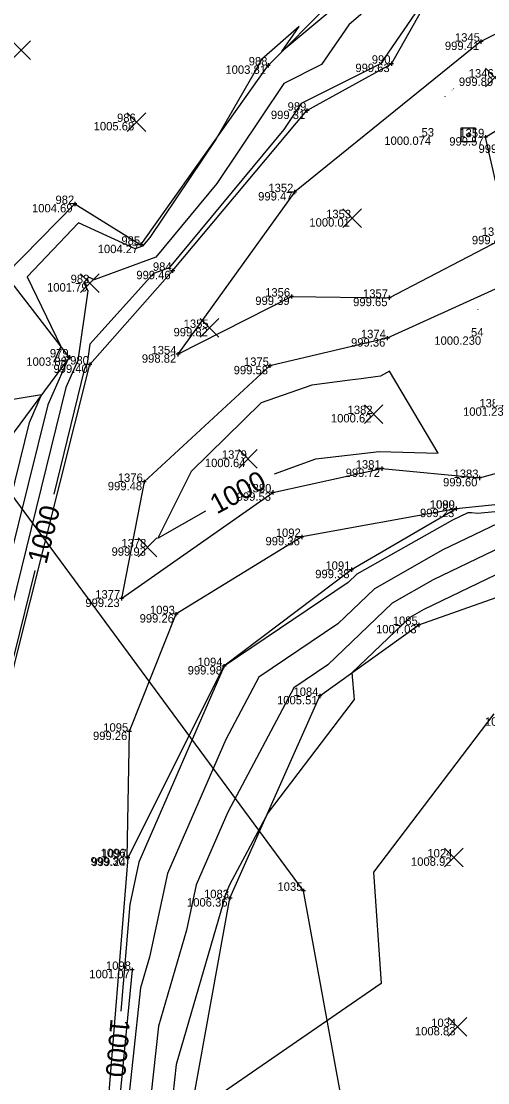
# Model space of a CAD drawing. Extents: x 2354693 to 2355622, y 637071 to 710080.
# Drawn here: x 2355257.5 to 2355324.2, y 709182.9 to 709334.6 of the extents above; entities that cross this region are included whole.
import ezdxf

# ---------------------------------------------------------------- set-up
doc = ezdxf.new("R2010")
doc.units = 0
for name, color, linetype in [('BR_P_Sub_Hidden', 7, 'Continuous'), ('BR_X_SV_Pier_Text', 7, 'Continuous'), ('DT_X_Contour_Major', 7, 'Continuous'), ('DT_X_Contour_Minor', 7, 'Continuous'), ('DT_X_Spot_Elev', 7, 'Continuous'), ('HY_X_Water_Edge', 7, 'Continuous'), ('SV_X_Break_Lines', 7, 'Continuous'), ('SV_X_Control_Cells_Found', 7, 'Continuous'), ('SV_X_Random_Point', 7, 'Continuous'), ('SV_X_Shot_Marker', 7, 'Continuous'), ('SV_X_Text_Elevation', 7, 'Continuous'), ('SV_X_Text_Name', 7, 'Continuous'), ('SV_X_Toe_of_Slope', 7, 'Continuous'), ('SV_X_Top_of_Bank', 7, 'Continuous'), ('VG_X_Tree_Line_Rt', 7, 'Continuous')]:
    doc.layers.add(name, color=color, linetype=linetype)

msp = doc.modelspace()

# ---------------------------------------------------------------- linework, layer by layer
at = {"layer": 'BR_P_Sub_Hidden'}
for points in [[(2355308.85, 709283.88), (2355308.16, 709283.78), (2355306.08, 709283.5), (2355304.5, 709283.29), (2355299.03, 709282.56), (2355291.81, 709280.05), (2355281.77, 709270.26), (2355277.03, 709260.71), (2355283.87, 709264.65)], [(2355293.71, 709269.93), (2355299.64, 709272.06), (2355308.68, 709273.09), (2355317.11, 709272.88), (2355310.14, 709284.57), (2355308.85, 709283.88)]]:
    msp.add_lwpolyline(points, dxfattribs=at)
at = {"layer": 'DT_X_Contour_Major'}
for points in [[(2355321.43, 709340.39), (2355320.59, 709340.2), (2355320.5, 709340.02), (2355317.25, 709340.56), (2355317.25, 709340.56), (2355317.21, 709340.59), (2355317.1, 709340.49), (2355308.88, 709328.46), (2355297.5, 709322.78), (2355295.04, 709319.11), (2355278.63, 709299.33), (2355276.4, 709298.5), (2355267.3, 709288.45), (2355266.91, 709285.66), (2355266.51, 709284.78), (2355262.13, 709266.99)], [(2355321.43, 709340.39), (2355320.59, 709340.2), (2355320.5, 709340.02), (2355317.25, 709340.56), (2355317.25, 709340.56), (2355317.21, 709340.59), (2355317.1, 709340.49), (2355308.88, 709328.46), (2355297.5, 709322.78), (2355295.04, 709319.11), (2355278.63, 709299.33), (2355276.4, 709298.5), (2355267.3, 709288.45), (2355266.91, 709285.66), (2355266.51, 709284.78), (2355262.13, 709266.99)], [(2355308.85, 709283.88), (2355308.16, 709283.78), (2355306.08, 709283.5), (2355304.5, 709283.29), (2355299.03, 709282.56), (2355291.81, 709280.05), (2355281.77, 709270.26), (2355277.03, 709260.71), (2355283.87, 709264.65)], [(2355293.71, 709269.93), (2355299.64, 709272.06), (2355308.68, 709273.09), (2355317.11, 709272.88), (2355310.14, 709284.57), (2355308.85, 709283.88)], [(2355328.11, 709264.75), (2355322.77, 709264.26), (2355321.89, 709264.33), (2355321.33, 709264.35), (2355319.14, 709263.3), (2355305.5, 709255.57), (2355304.26, 709254.39), (2355286.53, 709242.43), (2355286.48, 709242.36), (2355274.31, 709214.47), (2355273, 709208.41), (2355271.74, 709193.19)], [(2355328.11, 709264.75), (2355322.77, 709264.26), (2355321.89, 709264.33), (2355321.33, 709264.35), (2355319.14, 709263.3), (2355305.5, 709255.57), (2355304.26, 709254.39), (2355286.53, 709242.43), (2355286.48, 709242.36), (2355274.31, 709214.47), (2355273, 709208.41), (2355271.74, 709193.19)], [(2355259.45, 709256.12), (2355256.53, 709244.3), (2355256.24, 709243.32), (2355255.21, 709238.35), (2355247.24, 709204.27), (2355240.26, 709205.95), (2355238.9, 709200.49), (2355236.53, 709200.69), (2355234.37, 709199.64), (2355221.59, 709197.85), (2355209.81, 709203.68)], [(2355259.45, 709256.12), (2355256.53, 709244.3), (2355256.24, 709243.32), (2355255.21, 709238.35), (2355247.24, 709204.27), (2355240.26, 709205.95), (2355238.9, 709200.49), (2355236.53, 709200.69), (2355234.37, 709199.64), (2355221.59, 709197.85), (2355209.81, 709203.68)]]:
    msp.add_lwpolyline(points, dxfattribs=at)
at = {"layer": 'DT_X_Contour_Minor'}
for points in [[(2355326.53, 709342.57), (2355320.94, 709341.33), (2355320.35, 709340.1), (2355318.58, 709340.39), (2355318.48, 709340.45), (2355314.55, 709342.82), (2355314.31, 709342.97), (2355312.91, 709343.83), (2355311.95, 709344.59), (2355294.76, 709330.21), (2355297.24, 709333.79), (2355291.85, 709329.11), (2355290.92, 709327.42), (2355285.35, 709317.76), (2355275.87, 709303.68), (2355274.83, 709302.42), (2355273.77, 709302.03), (2355265.66, 709305.78), (2355258.36, 709298.04), (2355263.17, 709288.1), (2355262.13, 709285.92), (2355264.15, 709286.24), (2355261.28, 709279.75), (2355255.69, 709257.09)], [(2355326.53, 709342.57), (2355320.94, 709341.33), (2355320.35, 709340.1), (2355318.58, 709340.39), (2355318.48, 709340.45), (2355314.55, 709342.82), (2355314.31, 709342.97), (2355312.91, 709343.83), (2355311.95, 709344.59), (2355294.76, 709330.21), (2355297.24, 709333.79), (2355291.85, 709329.11), (2355290.92, 709327.42), (2355285.35, 709317.76), (2355275.87, 709303.68), (2355274.83, 709302.42), (2355273.77, 709302.03), (2355265.66, 709305.78), (2355258.36, 709298.04), (2355263.17, 709288.1), (2355262.13, 709285.92), (2355264.15, 709286.24), (2355261.28, 709279.75), (2355255.69, 709257.09)], [(2355323.98, 709341.48), (2355320.76, 709340.76), (2355320.42, 709340.06), (2355317.91, 709340.48), (2355317.86, 709340.51), (2355314.31, 709342.64), (2355304.35, 709334.06), (2355300.45, 709328.35), (2355295.04, 709325.64), (2355285.45, 709311.4), (2355276.73, 709300.87), (2355267.93, 709297.62), (2355267.15, 709297.98), (2355266.44, 709297.23), (2355267.01, 709296.07), (2355265.6, 709286.11), (2355263.89, 709282.26), (2355256.11, 709250.69)], [(2355323.98, 709341.48), (2355320.76, 709340.76), (2355320.42, 709340.06), (2355317.91, 709340.48), (2355317.86, 709340.51), (2355314.31, 709342.64), (2355304.35, 709334.06), (2355300.45, 709328.35), (2355295.04, 709325.64), (2355285.45, 709311.4), (2355276.73, 709300.87), (2355267.93, 709297.62), (2355267.15, 709297.98), (2355266.44, 709297.23), (2355267.01, 709296.07), (2355265.6, 709286.11), (2355263.89, 709282.26), (2355256.11, 709250.69)], [(2355258.66, 709277.24), (2355260.4, 709281.18), (2355246.4, 709278.91), (2355245.09, 709279.12), (2355242.59, 709271.24), (2355232.14, 709270.2), (2355237.45, 709251.15), (2355244.48, 709247.85), (2355245.62, 709241.89), (2355244.67, 709227.63), (2355248.78, 709240.19), (2355250.1, 709246.57), (2355255.27, 709263.49), (2355258.66, 709277.24)], [(2355258.66, 709277.24), (2355260.4, 709281.18), (2355246.4, 709278.91), (2355245.09, 709279.12), (2355242.59, 709271.24), (2355232.14, 709270.2), (2355237.45, 709251.15), (2355244.48, 709247.85), (2355245.62, 709241.89), (2355244.67, 709227.63), (2355248.78, 709240.19), (2355250.1, 709246.57), (2355255.27, 709263.49), (2355258.66, 709277.24)], [(2355325.65, 709262.82), (2355317.77, 709259.04), (2355308.02, 709253.51), (2355302.78, 709248.51), (2355291.49, 709240.89), (2355286.75, 709231.97), (2355278.41, 709212.85), (2355275.83, 709200.88), (2355274.55, 709196.51), (2355272.35, 709176.11)], [(2355325.65, 709262.82), (2355317.77, 709259.04), (2355308.02, 709253.51), (2355302.78, 709248.51), (2355291.49, 709240.89), (2355286.75, 709231.97), (2355278.41, 709212.85), (2355275.83, 709200.88), (2355274.55, 709196.51), (2355272.35, 709176.11)], [(2355329.97, 709261.3), (2355316.41, 709254.78), (2355310.53, 709251.45), (2355301.31, 709242.63), (2355296.45, 709239.35), (2355287.02, 709221.58), (2355282.5, 709211.23), (2355281.11, 709204.74), (2355277.11, 709191.02), (2355275.65, 709177.54)], [(2355329.97, 709261.3), (2355316.41, 709254.78), (2355310.53, 709251.45), (2355301.31, 709242.63), (2355296.45, 709239.35), (2355287.02, 709221.58), (2355282.5, 709211.23), (2355281.11, 709204.74), (2355277.11, 709191.02), (2355275.65, 709177.54)], [(2355334.29, 709259.77), (2355315.04, 709250.52), (2355313.05, 709249.39), (2355304.76, 709241.47), (2355305.1, 709237.69), (2355302.95, 709234.87), (2355292.79, 709221.56), (2355287.29, 709211.19), (2355286.6, 709209.61), (2355286.39, 709208.61), (2355279.66, 709185.54), (2355278.95, 709178.98)], [(2355334.29, 709259.77), (2355315.04, 709250.52), (2355313.05, 709249.39), (2355304.76, 709241.47), (2355305.1, 709237.69), (2355302.95, 709234.87), (2355292.79, 709221.56), (2355287.29, 709211.19), (2355286.6, 709209.61), (2355286.39, 709208.61), (2355279.66, 709185.54), (2355278.95, 709178.98)], [(2355325.08, 709235.63), (2355314.19, 709221.34), (2355307.85, 709213.04), (2355308.94, 709197.1), (2355286.27, 709181.51)], [(2355325.08, 709235.63), (2355314.19, 709221.34), (2355307.85, 709213.04), (2355308.94, 709197.1), (2355286.27, 709181.51)]]:
    msp.add_lwpolyline(points, dxfattribs=at)
at = {"layer": 'HY_X_Water_Edge'}
for points in [[(2355099.14, 709490.23), (2355112.83, 709450.59), (2355116.9, 709430.14), (2355110.74, 709408.55), (2355107.27, 709364.38), (2355126.09, 709328.02), (2355146.4, 709319.01), (2355178.16, 709243.86), (2355207.27, 709238.41), (2355228.23, 709233.04), (2355237.12, 709206.89), (2355247.9, 709203.67), (2355256.61, 709243.12), (2355267.3, 709285.53), (2355279.14, 709298.91), (2355298.35, 709321.78), (2355310.42, 709328.49), (2355317.24, 709340.56)], [(2355359.12, 709336.96), (2355357.91, 709341.69), (2355351.85, 709345.87), (2355323.23, 709331.64), (2355296.55, 709310.15), (2355279.9, 709286.98), (2355296.13, 709295.23), (2355310.1, 709295.06), (2355327.1, 709303.9), (2355323.88, 709317.99), (2355329.6, 709321.57), (2355359.12, 709336.96)], [(2355338.24, 709293.81), (2355335.55, 709300.96), (2355309.84, 709289.28), (2355293.06, 709285.33), (2355275.06, 709268.76), (2355271.82, 709252.1), (2355293.45, 709267.26), (2355309.04, 709270.66), (2355323.01, 709269.32), (2355355.38, 709278.14), (2355366.3, 709291.81), (2355368.89, 709301.06)], [(2355342.79, 709267.27), (2355319.66, 709264.93)], [(2355319.66, 709264.93), (2355297.62, 709260.9), (2355279.61, 709249.87), (2355272.94, 709233.09), (2355272.6, 709215.17)], [(2355272.75, 709215.1), (2355272.74, 709215.09), (2355269.55, 709175.73), (2355269.77, 709147.81), (2355269.19, 709105.65), (2355274.67, 709084.44), (2355274.45, 709045.7), (2355249.64, 708995.53), (2355233.3, 708975.07), (2355214.48, 708950.61), (2355202.85, 708934.67), (2355185.21, 708913.18), (2355155.78, 708878.52), (2355144.35, 708868.9), (2355107.99, 708834.31)]]:
    msp.add_lwpolyline(points, dxfattribs=at)
at = {"layer": 'SV_X_Break_Lines'}
msp.add_lwpolyline([(2355288.47, 709157.1), (2355279.67, 709145.96), (2355282.08, 709180.34), (2355287.34, 709209.31), (2355300.19, 709238.19), (2355314.34, 709248.33), (2355340.5, 709257.58), (2355343.4, 709262.66)], dxfattribs=at)
at = {"layer": 'SV_X_Control_Cells_Found'}
msp.add_lwpolyline([(2355320.41, 709319.32), (2355322.39, 709319.32), (2355322.39, 709317.34), (2355320.41, 709317.34), (2355320.41, 709319.32)], dxfattribs=at)
msp.add_circle((2355321.4, 709318.33), 0.2, dxfattribs=at)
at = {"layer": 'SV_X_Random_Point'}
for p, q in [((2355256.17, 709329.09), (2355258.84, 709331.76)), ((2355256.17, 709331.76), (2355258.84, 709329.09)), ((2355323.9, 709325.17), (2355326.57, 709327.84)), ((2355323.9, 709327.84), (2355326.57, 709325.17)), ((2355272.66, 709318.82), (2355275.33, 709321.49)), ((2355272.66, 709321.49), (2355275.33, 709318.82)), ((2355303.48, 709305.09), (2355306.14, 709307.76)), ((2355303.48, 709307.76), (2355306.14, 709305.09)), ((2355265.97, 709295.81), (2355268.64, 709298.48)), ((2355265.97, 709298.48), (2355268.64, 709295.81)), ((2355283.1, 709289.41), (2355285.77, 709292.08)), ((2355283.1, 709292.08), (2355285.77, 709289.41)), ((2355306.56, 709277.11), (2355309.22, 709279.78)), ((2355306.56, 709279.78), (2355309.22, 709277.11)), ((2355288.59, 709270.74), (2355291.25, 709273.41)), ((2355288.59, 709273.41), (2355291.25, 709270.74)), ((2355274.23, 709258.08), (2355276.9, 709260.75)), ((2355274.23, 709260.75), (2355276.9, 709258.08)), ((2355318.01, 709213.8), (2355320.68, 709216.47)), ((2355318.01, 709216.47), (2355320.68, 709213.8)), ((2355318.56, 709189.58), (2355321.22, 709192.25)), ((2355318.56, 709192.25), (2355321.22, 709189.58))]:
    msp.add_line(p, q, dxfattribs=at)
at = {"layer": 'SV_X_Shot_Marker'}
for p, q in [((2355323.53, 709331.64), (2355322.93, 709331.64)), ((2355323.23, 709331.94), (2355323.23, 709331.34)), ((2355293.11, 709328.24), (2355292.51, 709328.24)), ((2355292.81, 709328.54), (2355292.81, 709327.94)), ((2355310.72, 709328.49), (2355310.12, 709328.49)), ((2355310.42, 709328.79), (2355310.42, 709328.19)), ((2355298.65, 709321.78), (2355298.05, 709321.78)), ((2355298.35, 709322.08), (2355298.35, 709321.48)), ((2355324.18, 709317.99), (2355323.58, 709317.99)), ((2355323.88, 709318.29), (2355323.88, 709317.69)), ((2355296.85, 709310.15), (2355296.25, 709310.15)), ((2355296.55, 709310.45), (2355296.55, 709309.85)), ((2355265.46, 709308.45), (2355264.86, 709308.45)), ((2355265.16, 709308.75), (2355265.16, 709308.15)), ((2355274.87, 709302.63), (2355274.27, 709302.63)), ((2355274.57, 709302.93), (2355274.57, 709302.33)), ((2355279.44, 709298.91), (2355278.84, 709298.91)), ((2355279.14, 709299.21), (2355279.14, 709298.61)), ((2355296.43, 709295.23), (2355295.83, 709295.23)), ((2355296.13, 709295.53), (2355296.13, 709294.93)), ((2355310.4, 709295.06), (2355309.8, 709295.06)), ((2355310.1, 709295.36), (2355310.1, 709294.76)), ((2355310.14, 709289.28), (2355309.54, 709289.28)), ((2355309.84, 709289.58), (2355309.84, 709288.98)), ((2355264.37, 709286.84), (2355264.37, 709286.24)), ((2355280.2, 709286.98), (2355279.6, 709286.98)), ((2355279.9, 709287.28), (2355279.9, 709286.68)), ((2355264.67, 709286.54), (2355264.07, 709286.54)), ((2355267.6, 709285.53), (2355267, 709285.53)), ((2355267.3, 709285.83), (2355267.3, 709285.23)), ((2355293.36, 709285.33), (2355292.76, 709285.33)), ((2355293.06, 709285.63), (2355293.06, 709285.03)), ((2355309.34, 709270.66), (2355308.74, 709270.66)), ((2355309.04, 709270.96), (2355309.04, 709270.36)), ((2355275.36, 709268.76), (2355274.76, 709268.76)), ((2355275.06, 709269.06), (2355275.06, 709268.46)), ((2355323.31, 709269.32), (2355322.71, 709269.32)), ((2355323.01, 709269.62), (2355323.01, 709269.02)), ((2355293.75, 709267.26), (2355293.15, 709267.26)), ((2355293.45, 709267.56), (2355293.45, 709266.96)), ((2355319.96, 709264.93), (2355319.36, 709264.93)), ((2355319.96, 709264.93), (2355319.36, 709264.93)), ((2355319.66, 709265.23), (2355319.66, 709264.63)), ((2355319.66, 709265.23), (2355319.66, 709264.63)), ((2355297.92, 709260.9), (2355297.32, 709260.9)), ((2355297.62, 709261.2), (2355297.62, 709260.6)), ((2355304.72, 709256.51), (2355304.72, 709255.91)), ((2355305.02, 709256.21), (2355304.42, 709256.21)), ((2355272.12, 709252.1), (2355271.52, 709252.1)), ((2355271.82, 709252.4), (2355271.82, 709251.8)), ((2355279.91, 709249.87), (2355279.31, 709249.87)), ((2355279.61, 709250.17), (2355279.61, 709249.57)), ((2355314.64, 709248.33), (2355314.04, 709248.33)), ((2355314.34, 709248.63), (2355314.34, 709248.03)), ((2355286.48, 709242.75), (2355286.48, 709242.15)), ((2355286.78, 709242.45), (2355286.18, 709242.45)), ((2355300.49, 709238.19), (2355299.89, 709238.19)), ((2355300.19, 709238.49), (2355300.19, 709237.89)), ((2355273.24, 709233.09), (2355272.64, 709233.09)), ((2355272.94, 709233.39), (2355272.94, 709232.79)), ((2355272.6, 709215.47), (2355272.6, 709214.87)), ((2355272.74, 709215.39), (2355272.74, 709214.79)), ((2355272.9, 709215.17), (2355272.3, 709215.17)), ((2355273.04, 709215.09), (2355272.44, 709215.09)), ((2355287.64, 709209.31), (2355287.04, 709209.31)), ((2355287.34, 709209.61), (2355287.34, 709209.01)), ((2355298.15, 709210.36), (2355297.55, 709210.36)), ((2355297.85, 709210.66), (2355297.85, 709210.06)), ((2355273.66, 709199.07), (2355273.06, 709199.07)), ((2355273.36, 709199.37), (2355273.36, 709198.77))]:
    msp.add_line(p, q, dxfattribs=at)
at = {"layer": 'SV_X_Toe_of_Slope'}
for points in [[(2355099.14, 709490.23), (2355112.83, 709450.59), (2355116.9, 709430.14), (2355110.74, 709408.55), (2355107.27, 709364.38), (2355126.09, 709328.02), (2355146.4, 709319.01), (2355178.16, 709243.86), (2355207.27, 709238.41), (2355228.23, 709233.04), (2355237.12, 709206.89), (2355247.9, 709203.67), (2355256.61, 709243.12), (2355267.3, 709285.53), (2355279.14, 709298.91), (2355298.35, 709321.78), (2355310.42, 709328.49), (2355317.24, 709340.56)], [(2355359.12, 709336.96), (2355357.91, 709341.69), (2355351.85, 709345.87), (2355323.23, 709331.64), (2355296.55, 709310.15), (2355279.9, 709286.98), (2355296.13, 709295.23), (2355310.1, 709295.06), (2355327.1, 709303.9), (2355323.88, 709317.99), (2355329.6, 709321.57), (2355359.12, 709336.96)], [(2355338.25, 709293.89), (2355335.55, 709300.96), (2355309.84, 709289.28), (2355293.06, 709285.33), (2355275.06, 709268.76), (2355271.82, 709252.1), (2355293.45, 709267.26), (2355309.04, 709270.66), (2355323.01, 709269.32), (2355355.38, 709278.14), (2355366.3, 709291.81), (2355368.89, 709301.06)], [(2355342.79, 709267.27), (2355319.66, 709264.93), (2355304.72, 709256.21), (2355286.48, 709242.45), (2355272.74, 709215.09), (2355269.55, 709175.73), (2355269.77, 709147.81), (2355269.19, 709105.65), (2355274.67, 709084.44), (2355274.45, 709045.7), (2355249.64, 708995.53), (2355233.3, 708975.07), (2355214.48, 708950.61), (2355202.85, 708934.67), (2355185.21, 708913.18), (2355155.78, 708878.52), (2355144.35, 708868.9), (2355107.99, 708834.31)], [(2355319.66, 709264.93), (2355297.62, 709260.9), (2355279.61, 709249.87), (2355272.94, 709233.09), (2355272.6, 709215.17)]]:
    msp.add_lwpolyline(points, dxfattribs=at)
at = {"layer": 'SV_X_Top_of_Bank'}
for points in [[(2355100.08, 709490.73), (2355115.52, 709450.05), (2355117.98, 709430.72), (2355113.57, 709407.6), (2355111.71, 709364.49), (2355128.66, 709328.03), (2355150.44, 709319.86), (2355166.79, 709277.66), (2355166, 709276.87), (2355178.56, 709246.01), (2355206.83, 709240.61), (2355229.16, 709234.35), (2355238.05, 709208.04), (2355245.62, 709205.75), (2355249.4, 709246.95), (2355254.61, 709273.36), (2355264.37, 709286.54), (2355255.26, 709298.36), (2355265.16, 709308.45), (2355274.57, 709302.63), (2355292.81, 709328.24), (2355310.42, 709346), (2355315.95, 709345.13)], [(2355273.36, 709199.07), (2355271.07, 709175.55), (2355271.92, 709154.64), (2355272.23, 709141.56), (2355270.63, 709105.68), (2355275.83, 709084.35), (2355276.25, 709045.62), (2355250.74, 708994.59), (2355235.32, 708973.62), (2355222.78, 708949.56), (2355205.08, 708933.16), (2355186.58, 708911.43), (2355156.5, 708876.84), (2355146.53, 708867.02), (2355127.53, 708842.2), (2355110.99, 708831.54)]]:
    msp.add_lwpolyline(points, dxfattribs=at)
at = {"layer": 'VG_X_Tree_Line_Rt'}
msp.add_lwpolyline([(2355286.87, 709031.33), (2355312.43, 709075.83), (2355322.75, 709120.09), (2355304.91, 709171.78), (2355297.85, 709210.36), (2355206.48, 709334.22), (2355207.86, 709373.6), (2355249.36, 709399.77), (2355239.7, 709433.16), (2355219.43, 709459.42), (2355185.29, 709497.16), (2355152.29, 709534.91)], dxfattribs=at)

# ---------------------------------------------------------------- texts
at = {"layer": 'BR_P_Sub_Hidden'}
msp.add_text('1000', height=2.8, rotation=28.2249, dxfattribs=at).set_placement((2355285.45, 709264.09))
at = {"layer": 'BR_X_SV_Pier_Text'}
msp.add_text('999.151', height=1.2, dxfattribs=at).set_placement((2355322.88, 709315.75))
at = {"layer": 'DT_X_Contour_Major'}
for rotation, p in [(28.2249, (2355285.45, 709264.09)), (76.1515, (2355261.08, 709256.89)), (76.1515, (2355261.08, 709256.89)), (264.9676, (2355270.28, 709192.18)), (264.9676, (2355270.28, 709192.18))]:
    msp.add_text('1000', height=2.8, rotation=rotation, dxfattribs=at).set_placement(p)
at = {"layer": 'DT_X_Spot_Elev'}
for p in [(2355319.01, 709324.66), (2355319.22, 709324.82), (2355317.87, 709323.73), (2355322.65, 709293.3)]:
    msp.add_text('999', height=0.14, rotation=360, dxfattribs=at).set_placement(p)
at = {"layer": 'SV_X_Text_Elevation'}
for s, p in [('999.41', (2355318.07, 709330.44)), ('1003.81', (2355286.69, 709327.04)), ('999.63', (2355305.27, 709327.29)), ('999.89', (2355320.07, 709325.31)), ('999.31', (2355293.19, 709320.58)), ('1005.68', (2355267.85, 709318.96)), ('1000.074', (2355309.41, 709316.89)), ('999.57', (2355318.7, 709316.79)), ('999.47', (2355291.37, 709308.95)), ('1004.69', (2355259.03, 709307.25)), ('1000.01', (2355298.69, 709305.22)), ('999.41', (2355321.93, 709302.7)), ('1004.27', (2355268.43, 709301.43)), ('999.46', (2355273.95, 709297.71)), ('1001.79', (2355261.18, 709295.95)), ('999.39', (2355290.96, 709294.03)), ('999.65', (2355304.95, 709293.86)), ('999.82', (2355279.27, 709289.55)), ('999.36', (2355304.65, 709288.08)), ('1000.230', (2355316.56, 709288.34)), ('998.82', (2355274.74, 709285.78)), ('1003.88', (2355258.22, 709285.34)), ('999.40', (2355262.1, 709284.33)), ('999.58', (2355287.87, 709284.13)), ('1001.23', (2355320.67, 709278.2)), ('1000.62', (2355301.77, 709277.25)), ('1000.64', (2355283.75, 709270.87)), ('999.72', (2355303.88, 709269.46)), ('999.48', (2355269.87, 709267.56)), ('999.60', (2355317.81, 709268.12)), ('999.53', (2355288.3, 709266.06)), ('999.23', (2355314.51, 709263.73)), ('999.23', (2355314.51, 709263.73)), ('999.36', (2355292.42, 709259.7)), ('999.93', (2355270.41, 709258.21)), ('999.38', (2355299.53, 709255.01)), ('999.23', (2355266.66, 709250.9)), ('999.26', (2355274.42, 709248.67)), ('1007.03', (2355308.23, 709247.13)), ('999.98', (2355281.29, 709241.25)), ('1005.51', (2355294.07, 709236.99)), ('1008.49', (2355323.8, 709233.93)), ('999.26', (2355267.75, 709231.89)), ('999.30', (2355267.4, 709213.97)), ('999.24', (2355267.53, 709213.89)), ('1008.92', (2355313.22, 709213.93)), ('1006.36', (2355281.19, 709208.11)), ('1001.07', (2355267.22, 709197.87)), ('1008.83', (2355313.78, 709189.71))]:
    msp.add_text(s, height=1.2, dxfattribs=at).set_placement(p)
at = {"layer": 'SV_X_Text_Name'}
for s, p in [('1345', (2355319.51, 709331.64)), ('988', (2355290.02, 709328.24)), ('990', (2355307.62, 709328.49)), ('1346', (2355321.48, 709326.51)), ('989', (2355295.58, 709321.78)), ('986', (2355271.19, 709320.16)), ('53', (2355314.73, 709318.09)), ('1359', (2355320.14, 709317.99)), ('1352', (2355292.83, 709310.15)), ('982', (2355262.39, 709308.45)), ('1353', (2355301.09, 709306.42)), ('1358', (2355323.34, 709303.9)), ('985', (2355271.81, 709302.63)), ('984', (2355276.32, 709298.91)), ('983', (2355264.55, 709297.15)), ('1356', (2355292.37, 709295.23)), ('1357', (2355306.36, 709295.06)), ('1355', (2355280.72, 709290.75)), ('1374', (2355306.06, 709289.28)), ('54', (2355321.81, 709289.54)), ('1354', (2355276.12, 709286.98)), ('979', (2355261.59, 709286.54)), ('980', (2355264.49, 709285.53)), ('1375', (2355289.34, 709285.33)), ('1384', (2355323, 709279.4)), ('1382', (2355304.16, 709278.45)), ('1379', (2355286.18, 709272.07)), ('1381', (2355305.32, 709270.66)), ('1376', (2355271.3, 709268.76)), ('1383', (2355319.3, 709269.32)), ('1380', (2355289.68, 709267.26)), ('1090', (2355315.9, 709264.93)), ('1089', (2355315.93, 709264.93)), ('1092', (2355293.89, 709260.9)), ('1378', (2355271.81, 709259.41)), ('1091', (2355300.99, 709256.21)), ('1377', (2355268.07, 709252.1)), ('1093', (2355275.89, 709249.87)), ('1085', (2355310.62, 709248.33)), ('1094', (2355282.7, 709242.45)), ('1084', (2355296.42, 709238.19)), ('1095', (2355269.22, 709233.09)), ('1096', (2355268.85, 709215.17)), ('1097', (2355269, 709215.09)), ('1024', (2355315.57, 709215.13)), ('1035', (2355294.13, 709210.36)), ('1083', (2355283.63, 709209.31)), ('1098', (2355269.61, 709199.07)), ('1034', (2355316.11, 709190.91))]:
    msp.add_text(s, height=1.2, dxfattribs=at).set_placement(p)

doc.saveas('drawing.dxf')
